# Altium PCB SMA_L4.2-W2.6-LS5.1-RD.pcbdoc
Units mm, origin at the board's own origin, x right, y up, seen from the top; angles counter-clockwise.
Board outline 19.6 x 15.78 mm, 2 copper layers (Top Layer, Bottom Layer), stack 0 mm thick; 1 components, 0 nets, 2 pads, 0 vias.
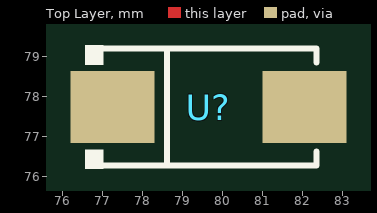
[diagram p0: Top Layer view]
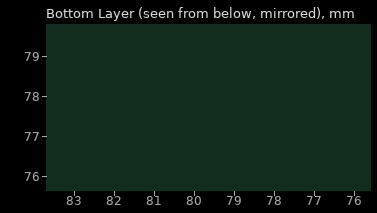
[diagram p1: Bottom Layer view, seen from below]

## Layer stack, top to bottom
Top Layer: signal copper (thickness not stored)
Bottom Layer: signal copper (thickness not stored)

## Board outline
89.45,69.85 69.85,69.85 69.85,85.63 89.45,85.63

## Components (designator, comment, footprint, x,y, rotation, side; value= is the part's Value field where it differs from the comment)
U? "" SMA_L4.2-W2.6-LS5.1-RD 79.65,77.74 r0 top

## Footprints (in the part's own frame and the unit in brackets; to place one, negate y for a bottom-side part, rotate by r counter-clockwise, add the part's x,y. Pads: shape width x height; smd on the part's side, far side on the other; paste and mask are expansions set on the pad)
SMA_L4.2-W2.6-LS5.1-RD [mm]
  rect 2.1x1.8 smd: 1(-2.4,0) 2(2.4,0)
  silkscreen extent -3.08,-1.54 2.7,1.54

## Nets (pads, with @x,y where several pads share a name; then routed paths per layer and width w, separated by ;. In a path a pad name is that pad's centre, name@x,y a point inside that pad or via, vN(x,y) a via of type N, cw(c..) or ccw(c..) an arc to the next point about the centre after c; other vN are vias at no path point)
pads on no net: U?.1 U?.2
